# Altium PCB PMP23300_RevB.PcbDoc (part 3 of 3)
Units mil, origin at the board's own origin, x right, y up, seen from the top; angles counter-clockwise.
Board outline 3834 x 2383 mil, 4 copper layers (Top Layer 1, Signal Layer 2, Signal Layer 3, Bottom Layer 1), stack 70.112 mil thick; 203 components, 126 nets, 635 pads, 226 vias.
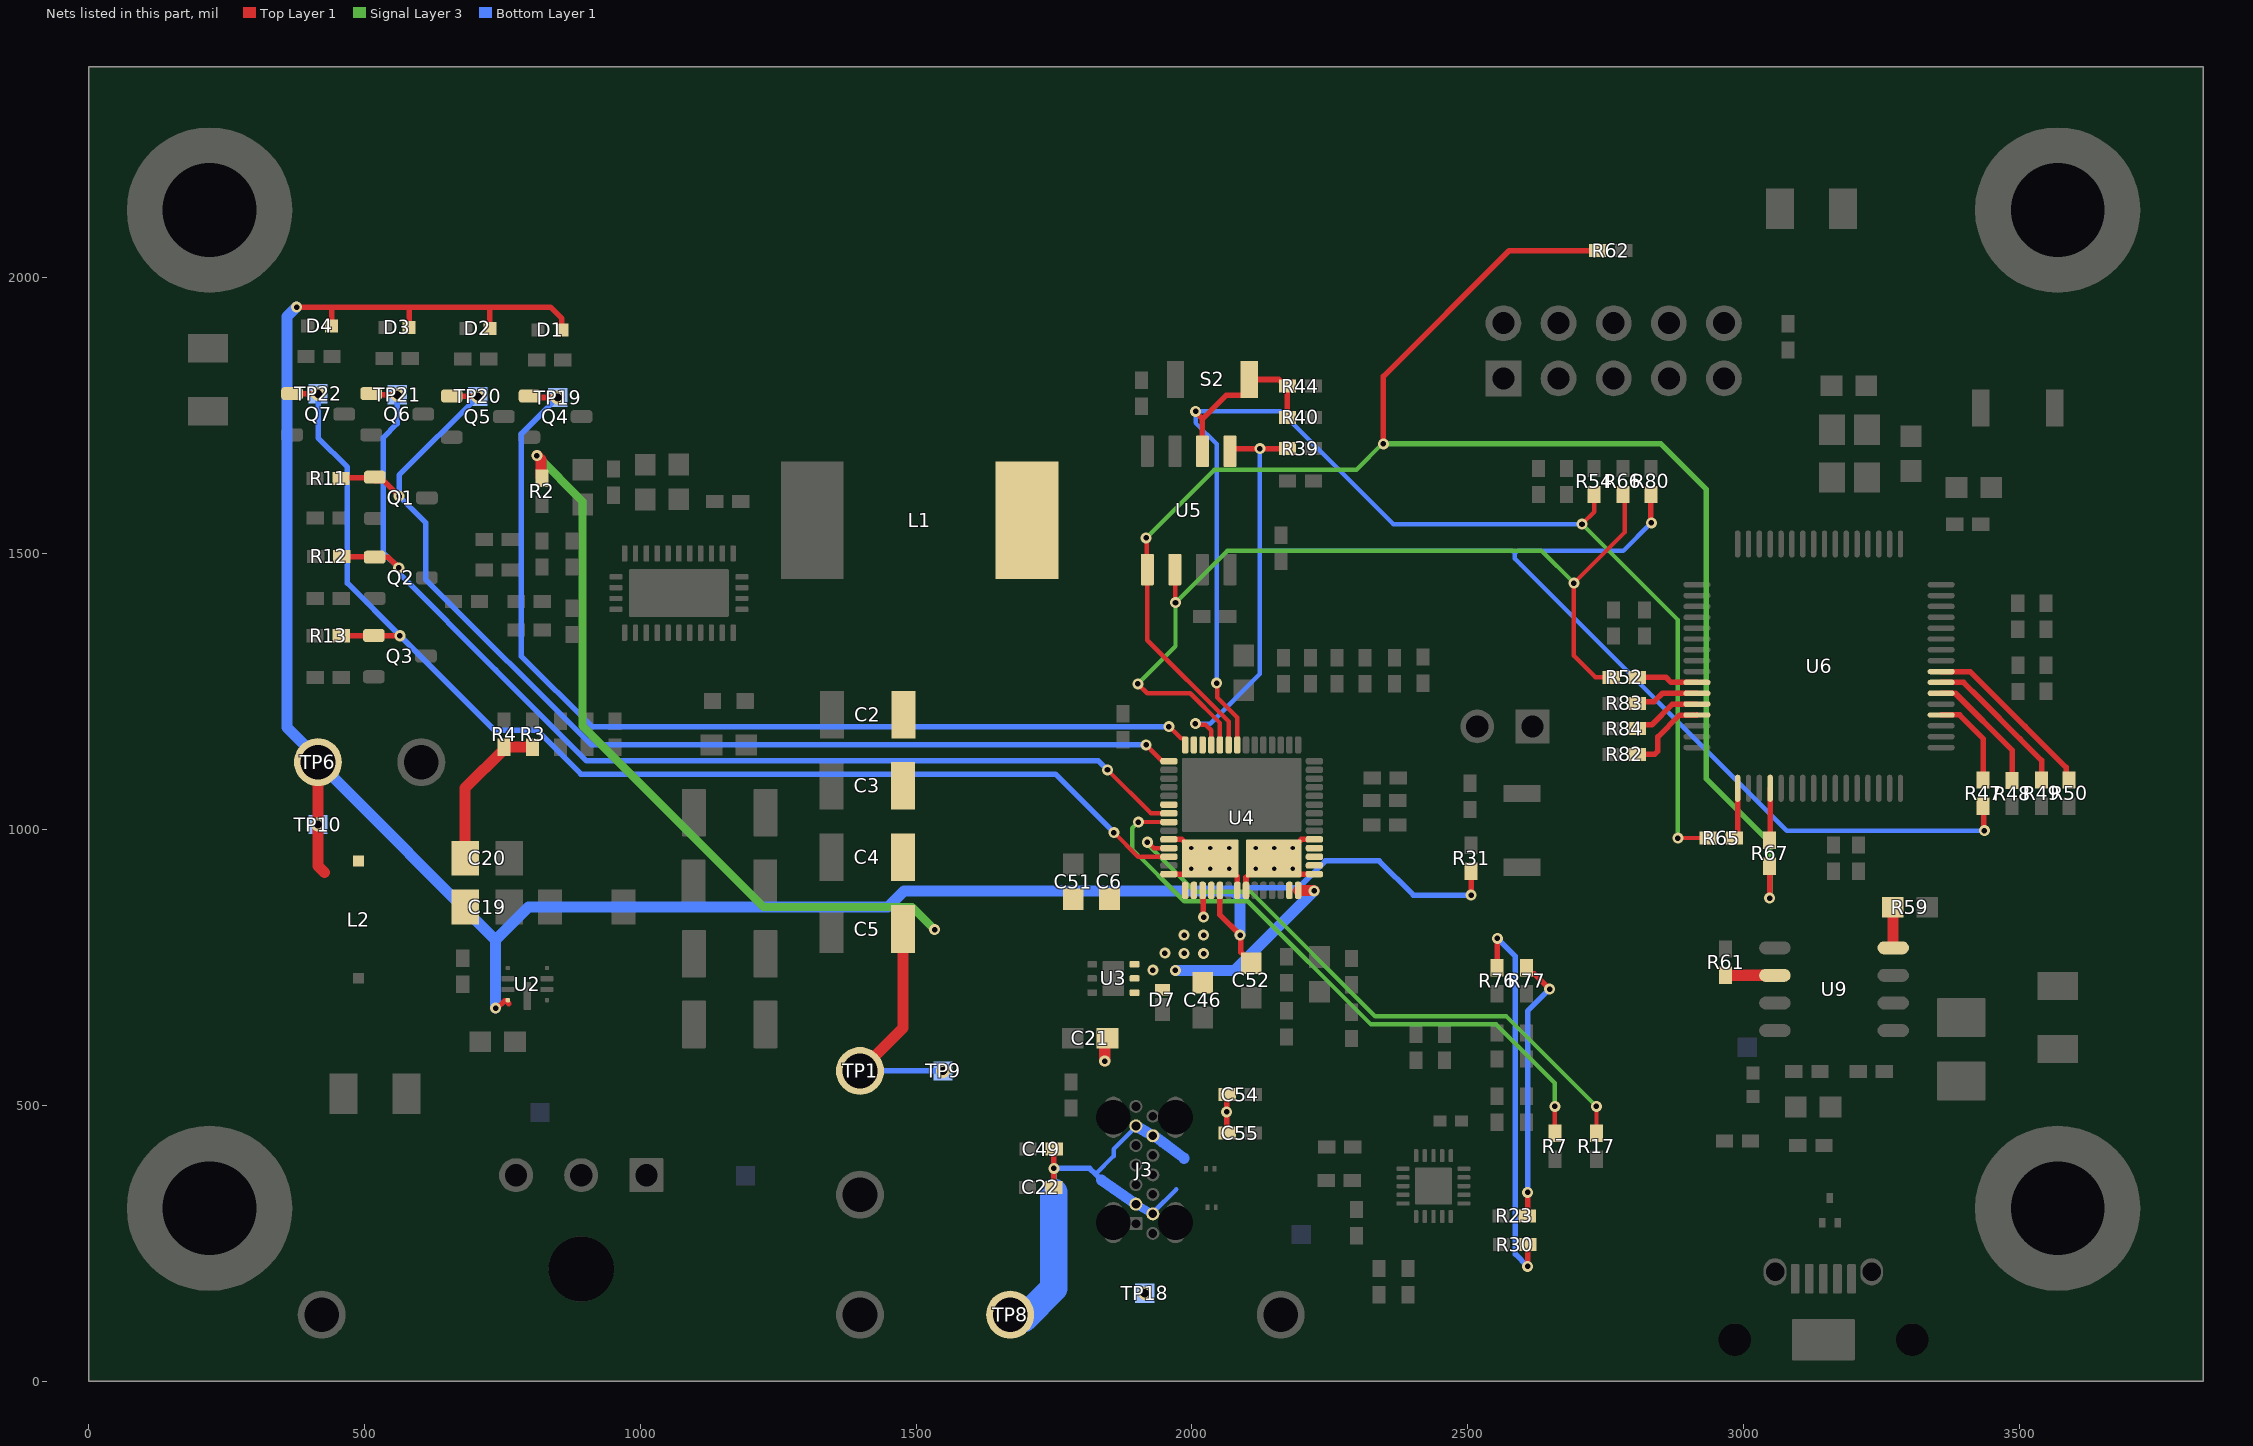
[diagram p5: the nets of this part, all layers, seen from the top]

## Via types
v1: diameter 20, hole 10, Top Layer 1 to Bottom Layer 1, tented top, 93 vias
v2: diameter 20, hole 10, Top Layer 1 to Bottom Layer 1, 67 vias
v3: diameter 19.68, hole 7.87, Top Layer 1 to Bottom Layer 1, 29 vias
v4: diameter 20, hole 10, Top Layer 1 to Bottom Layer 1, tented both sides, 20 vias
v5: diameter 25, hole 15, Top Layer 1 to Bottom Layer 1, 8 vias
v6: diameter 19.68, hole 7.87, Top Layer 1 to Bottom Layer 1, tented both sides, 6 vias
v7: diameter 25, hole 15, Top Layer 1 to Bottom Layer 1, tented top, 3 vias

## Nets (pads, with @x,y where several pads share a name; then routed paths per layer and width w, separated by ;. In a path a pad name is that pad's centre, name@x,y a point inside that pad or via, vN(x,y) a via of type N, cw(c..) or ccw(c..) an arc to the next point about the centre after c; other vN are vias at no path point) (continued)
NetR47_1: R47.1 U6.20 | length 169
  Top Layer 1 w10: U6.20@3358.82,1207.62 3392.25,1207.62 3434.95,1164.92 R47.1@3434.95,1089.71
NetR48_1: R48.1 U6.22 | length 226.3
  Top Layer 1 w10: U6.22@3358.82,1246.99 3384.29,1246.99 3487.28,1144.01 R48.1@3487.28,1088.86
NetR49_1: R49.1 U6.23 | length 276.2
  Top Layer 1 w10: U6.23@3358.82,1266.68 3358.9,1266.6 3399.66,1266.6 3429.65,1236.6 3502.01,1164.25 3540.79,1125.47 R49.1@3540.79,1089.71
NetR50_1: R50.1 U6.24 | length 323.7
  Top Layer 1 w10: U6.24@3358.82,1286.36 3411.44,1286.36 3453.11,1244.7 3510.92,1186.88 3585.16,1112.64 3585.16,1095.54 R50.1@3591,1089.71
NetR52_1: R52.1 U6.58 | length 119.4
  Top Layer 1 w10: R52.1@2812.53,1281.03 R52.1@2807.5,1276 2859.53,1276 2868.94,1266.6 2915.83,1266.6 U6.58@2915.91,1266.68
NetR59_1: R59.1 U9.8 | length 85.2
  Top Layer 1 w20: R59.1@3270.77,858.79 3271.36,858.2 3271.36,786 U9.8@3271.95,785.41 3272.64,786.1 U9.8@3283.04,786.1
NetR61_1: R61.1 U9.2 | length 89.8
  Top Layer 1 w20: R61.1@2967.81,736 2968.11,735.7 3057.09,735.7 U9.2@3057.38,735.41
NetR65_1: R65.1 U6.1 | length 99.2
  Top Layer 1 w10: R65.1@2982.15,993.3 R65.1@2990.93,984.53 ; R65.1@2989.73,987.99 U6.1@2989.73,1074.75
NetR67_1: R67.1 U6.4 | length 98.7
  Top Layer 1 w10: U6.4@3048.78,1074.75 3048.86,1074.67 3048.86,983.14 R67.1@3053.82,978.18
NetR82_1: R82.1 U6.61 | length 153.1
  Top Layer 1 w10: R82.1@2807.5,1136.27 2839.26,1136.27 2845.11,1142.13 2845.11,1167.96 2884.7,1207.54 2915.83,1207.54 U6.61@2915.91,1207.62
NetR83_1: R83.1 U6.59 | length 115.9
  Top Layer 1 w10: R83.1@2807.5,1228.82 2810.37,1231.68 2838.25,1231.68 2853.56,1246.99 U6.59@2915.91,1246.99
NetR84_1: R84.1 U6.60 | length 126.8
  Top Layer 1 w10: R84.1@2807.5,1183.01 2814.31,1189.82 2833.99,1189.82 2871.4,1227.23 2915.83,1227.23 U6.60@2915.91,1227.31
NetU4_7: U4.7 U4.52 U4.56 U4.57@2033.37,947.61 | length 137.4
  Top Layer 1 w10: U4.56@1958.56,919.06 1989.07,919.06 v3(1998.92,928.91) ; U4.52@1958.56,982.05 1982.18,982.05 1997.93,966.31 v3(1998.92,966.31) ; v3(2067.81,928.91) 2068.8,928.91 2082.58,915.13 U4.7@2082.58,889.53
  other v3: 2033.37,928.91 2033.37,966.31 2067.81,966.31
NetU4_8: U4.8 U4.15 U4.19 U4.58@2148.52,947.61 | length 135.2
  Top Layer 1 w10: U4.8@2098.33,889.53 2098.33,913.16 U4.58@2114.07,928.91 ; v6(2182.97,928.91) 2192.81,919.06 U4.15@2222.34,919.06 ; v6(2182.97,966.31) 2198.72,982.05 U4.19@2222.34,982.05
  other v6: 2116.02,928.91 2149.5,928.91 2116.02,966.31 2149.5,966.31
P3V3: C19.1 C20.1 C52.1 D1.1 D2.1 D3.1 D4.1 L2.2 R3.1 R4.1 R31.2 TP6.1 TP10.1 U2.8 U4.5 | length 4802.8
  Top Layer 1 w10: v2(376.92,1947.34) 836.85,1947.34 857.89,1926.3 857.89,1905.93 D1.1@858.04,1905.78 ; D4.1@440.41,1912.96 440.41,1945.48 ; D3.1@580.94,1910.52 580.94,1946.75 ; D2.1@727.38,1908.57 727.38,1946.94 ; v2(737.91,676.08) 740.61,676.08 753.91,689.39 756.71,689.39 761.86,684.23 ; U4.5@2051.08,889.53 2051.08,845.23 2088.98,807.34 2088.98,777.61 2094.61,771.97 C52.1@2104.57,771.97 ; v1(2506.48,881) R31.2@2506.48,924.16
  Top Layer 1 w20: TP6.1@415.57,1122.14 415.57,933.65 427.31,921.91 ; C20.1@682.61,947.94 682.61,1074.95 753.06,1145.4 R4.1@753.06,1149.34 R3.1@804.71,1149.34
  Bottom Layer 1 w10: v7(415.57,1008.91) TP6.1@415.57,1114.11 ; 2087.75,874.54 2107.82,894.61 2193.94,894.61 2242.37,943.03 2339.73,943.03 2401.76,881 v1(2506.48,881)
  Bottom Layer 1 w20: v2(376.92,1947.34) 359.61,1930.03 359.61,1184.67 415.57,1128.71 TP6.1@415.57,1122.14 423.6,1122.14 423.6,1114.11 737.91,799.81 ; v2(737.91,676.08) 737.91,799.81 ; v1(2087.75,808.56) 2087.75,876.98 2076.04,888.69 1478.4,888.69 1449.07,859.36 797.46,859.36 737.91,799.81
PD_USB_N: R17.1 U4.53 | length 1106.7
  Top Layer 1 w8: v2(1919.63,976.88) 1920.24,976.88 1930.81,966.31 U4.53@1958.56,966.31 ; R17.1@2733.79,449.17 v2(2733.79,497.86)
  Signal Layer 3 w8: v2(1919.63,976.88) 1919.63,973.63 1925.37,967.89 1925.37,967.51 2005.41,887.47 2106.29,887.47 2332.68,661.08 2570.57,661.08 v2(2733.79,497.86)
PD_USB_P: R7.1 U4.50 | length 1142.2
  Top Layer 1 w8: v2(1903.07,1013.52) U4.50@1958.55,1013.54 ; R7.1@2658.25,449.27 v1(2658.25,497.86)
  Signal Layer 3 w8: v2(1903.07,1013.52) 1891.79,1002.24 1891.79,964.79 1986.48,870.1 2101.43,870.1 2324.95,646.59 2552,646.59 2658.25,540.33 v1(2658.25,497.86)
PDO_0: Q4.1 TP19.1 U4.42 | length 1813.2
  Top Layer 1 w8: v2(1958.56,1186.41) 1959.73,1186.41 1981.08,1165.06 1986.18,1165.06 1988.09,1163.16 U4.42@1988.09,1153.31
  Top Layer 1 w10: Q4.1@809.29,1783.27 v5(850.16,1783.27)
  Bottom Layer 1 w10: v5(850.16,1783.27) 784.48,1717.59 784.48,1314.07 912.14,1186.41 v2(1958.56,1186.41)
PDO_1: Q1.1 Q5.1 R11.2 TP20.1 U4.43 | length 2055.2
  Top Layer 1 w8: R11.2@457.47,1636.55 R11.2@458.6,1637.68 ; Q1.1@517,1637.68 Q1.1@518.14,1636.55 ; Q1.1@518.7,1632.91 518.7,1637.12 Q1.1@518.7,1638.82 ; v2(1917.26,1153.31) 1933.03,1137.54 1944.88,1125.69 1956.66,1125.69 U4.43@1958.56,1123.79
  Top Layer 1 w10: R11.2@458.6,1637.68 Q1.1@517,1637.68 ; Q1.1@518.14,1636.55 Q1.1@518.7,1637.12 ; Q1.1@518.7,1632.91 519.05,1632.56 534.8,1632.56 v2(562.77,1604.59) ; Q5.1@669.39,1785.53 669.58,1785.34 705.26,1785.34 v5(705.45,1785.15)
  Bottom Layer 1 w10: v5(705.45,1785.15) 562.77,1642.47 v2(562.77,1604.59) 611,1556.36 611,1453.56 910.8,1153.76 1916.81,1153.76 v2(1917.26,1153.31)
PDO_2: Q2.1 Q6.1 R12.2 TP21.1 U4.49 | length 2072.1
  Top Layer 1 w8: R12.2@458.96,1495.1 R12.2@459.65,1494.41 ; Q2.1@517.76,1494.41 Q2.1@518.45,1493.72 ; v2(1847.2,1108.04) 1925.94,1029.3 U4.49@1958.56,1029.3
  Top Layer 1 w10: R12.2@459.65,1494.41 Q2.1@517.76,1494.41 ; Q2.1@518.45,1493.72 532.22,1493.24 543.19,1493.24 557.17,1479.26 v2(562.11,1474.32) ; Q6.1@520.88,1788 v5(559.29,1788)
  Bottom Layer 1 w10: v5(559.29,1788) 559.29,1735.73 533.79,1710.23 533.79,1502.64 564.02,1472.41 564.02,1463.27 737.91,1289.39 902.73,1124.57 1830.67,1124.57 v2(1847.2,1108.04)
PDO_3: Q3.1 Q7.1 R13.2 TP22.1 U4.54 | length 2198.9
  Top Layer 1 w8: v2(1858.81,994.39) 1902.63,950.56 U4.54@1958.56,950.56
  Top Layer 1 w10: Q7.1@380.39,1789.9 v7@415.82,1789.9 ; R13.2@461.19,1351.29 v2(564.21,1351.29)
  Bottom Layer 1 w10: v7(415.85,1789.86) 415.85,1710.12 468.92,1657.05 468.92,1446.58 v2(564.21,1351.29) 735.24,1180.27 812.47,1180.27 892.27,1100.47 1752.72,1100.47 v2(1858.81,994.39)
PP_EXT2_EN: U4.48
SBU_N: R30.1 R76.2 | length 711.6
  Top Layer 1 w10: R76.2@2553.51,747.97 2553.78,748.24 2553.78,802.42 v1(2554.05,802.69) ; v1(2608.88,207.99) R30.1@2608.88,247.25
  Bottom Layer 1 w10: v1(2554.05,802.69) 2586.68,770.06 2586.68,230.19 v1(2608.88,207.99)
SBU_P: R23.1 R77.2 | length 488.3
  Top Layer 1 w10: R77.2@2607.18,749.14 2607.18,745.2 2613.99,738.39 2621.33,738.39 v1(2648.99,710.72) ; R23.1@2608.03,299.41 2608.88,300.26 v1(2608.88,341.98)
  Bottom Layer 1 w10: v1(2608.88,341.98) 2608.88,670.61 v1(2648.99,710.72)
SPI_CLK: R52.2 R66.2 U4.38 U5.6 | length 1653.9
  Top Layer 1 w8: v2(1902.26,1263.86) 1919.05,1247.06 1997.18,1247.06 2051.08,1193.16 U4.38@2051.08,1153.31 ; U5.6@1969.33,1470.32 1969.91,1469.74 1969.91,1411.89 v1(1970.48,1411.32) ; R52.2@2760.26,1276 2731.93,1276 2692.86,1315.07 v2(2692.86,1446.77) 2784.81,1538.71 2784.81,1604.2 R66.2@2781.61,1607.41
  Signal Layer 3 w8: v2(1902.26,1263.86) 1970.48,1332.09 v1(1970.48,1411.32) 2064.27,1505.1 2634.53,1505.1 v2(2692.86,1446.77)
SPI_CSZ: R39.2 R47.2 R80.2 U4.39 U5.1 | length 2621
  Top Layer 1 w8: v2(2006.61,1191.95) 2008.9,1189.66 2025.45,1189.66 2035.33,1179.77 U4.39@2035.33,1153.31
  Top Layer 1 w10: U5.1@2073.27,1690.79 v2(2123.37,1690.79) R39.2@2173.47,1690.79 ; R80.2@2832.61,1607.41 2832.61,1556.83 v4@2833.99,1555.45 ; R47.2@3434.95,1042.46 3435.99,1041.42 3435.99,998.95 v4(3437.03,997.91)
  Bottom Layer 1 w8: v2(2006.61,1191.95) 2033.34,1191.95 2123.37,1281.98 2123.37,1505.1 ; v2(2123.37,1690.79) 2123.37,1505.1 ; v4(2833.3,1556.14) 2782.26,1505.1 2590.61,1505.1 2585.92,1500.41 ; v4(3437.03,997.91) 3078.89,997.91 2597.39,1479.41 2585.92,1490.88 2585.92,1500.41 ; 2123.37,1505.1 2581.24,1505.1 2585.92,1500.41
SPI_MISO: R40.2 R44.2 R54.2 R65.2 S2.1 U4.36 U5.2 | length 2492.3
  Top Layer 1 w8: v1(2045.09,1265.32) 2046.3,1264.11 2046.3,1239.32 2082.58,1203.05 U4.36@2082.58,1153.31 ; v4(2707.56,1553.79) 2729.61,1575.84 R54.2@2729.61,1607.41 ; v4(2881.42,984.53) R65.2@2936.48,984.53
  Top Layer 1 w10: v1@2006.91,1756.32 2019.33,1743.9 ; U5.2@2019.33,1686.85 2019.33,1743.9 ; S2.1@2093.59,1787.46 2062.9,1787.46 2019.33,1743.9 ; S2.1@2104.34,1815.93 2157.72,1815.93 2169.53,1804.12 R44.2@2173.47,1804.12 ; R40.2@2173.47,1747.03 R44.2@2173.47,1804.12 ; R44.2@2184.22,1810.93 2177.41,1804.12 R44.2@2173.47,1804.12
  Signal Layer 3 w8: v4(2707.56,1553.79) 2881.42,1379.93 v4(2881.42,984.53)
  Bottom Layer 1 w8: v1(2045.09,1265.32) 2045.09,1699 2006.91,1737.18 v1(2006.91,1758.25) 2160.67,1758.25 2365.13,1553.79 v4(2707.56,1553.79)
SPI_MOSI: R62.1 R67.2 U4.37 U5.5 | length 3009.5
  Top Layer 1 w8: v2(1917.26,1528.69) 1918.29,1527.65 1918.29,1471.35 1919.33,1470.32 1919.33,1343.29 2066.83,1195.8 U4.37@2066.83,1153.31
  Top Layer 1 w10: v1(2347.48,1699.04) 2347.48,1821.62 2575.61,2049.76 R62.1@2736.05,2049.76 ; v4(3047.75,875.75) R67.2@3047.75,933.42
  Signal Layer 3 w8: v2(1917.26,1528.69) 2041.06,1652.49 2298.62,1652.49 v1@2346.79,1700.66
  Signal Layer 3 w10: v1(2347.48,1699.04) 2850.57,1699.04 2933,1616.6 2933,1091.73 3047.75,976.98 v4(3047.75,875.75)
SSMX_DP: U4.16
SSMX_FLIP: U4.17
SSMX_USB3: U4.18
SWD_CLK: U4.40
SWD_DATA: U4.41
VBUS: C21.2 C22.1 C46.1 C49.1 C54.1 C55.1 D7.1 J3.A4 J3.A9 J3.B4 J3.B9 TP8.1 TP18.1 U3.4 U3.5 U3.6 U4.3 U4.4 U4.13 U4.14 | length 1341.2
  Top Layer 1 w10: C22.1@1749.79,359.08 v1(1749.79,385.71) C49.1@1749.79,412.33 ; J3.A4@1898.73,320.7 J3.A4@1898.73,322.82 ; U4.3@2019.59,889.53 2020.46,888.67 2020.46,842.14 v1(2021.33,841.27) ; C55.1@2063.09,457.77 2063.09,518.3 C54.1@2064.13,519.34 ; U4.14@2192.81,889.53 U4.14@2193.24,889.11 ; v1@2221.55,889.11 v1(2221.98,888.68)
  Top Layer 1 w20: v1(1842.21,579.95) 1842.21,616.56 C21.2@1847.2,621.55 ; U4.14@2193.24,889.11 v1@2221.55,889.11
  Bottom Layer 1 w8: 1825.48,375.05 1858.21,407.78 1858.21,420.4 1898.73,460.92 J3.A9@1898.73,462.43 ; J3.B9@1929.44,305.17 1972.16,347.89
  Bottom Layer 1 w10: 1749.79,342.03 v1(1749.79,385.71) 1814.82,385.71 1825.48,375.05 1836.13,364.4 ; J3.B9@1926.83,305.59 J3.B9@1929.44,302.98 J3.B9@1929.44,305.17
  Bottom Layer 1 w15: J3.A4@1898.73,320.7 J3.B9@1929.44,302.98
  Bottom Layer 1 w20: 1836.13,364.4 J3.A4@1898.73,320.7 ; J3.A9@1898.73,462.43 1919.37,450.52 J3.B4@1929.44,444.71 ; J3.B4@1931.28,444.71 1948.12,432.2 1986.18,403.92 ; v1(1970.35,744.36) 2077.66,744.36 v1(2221.98,888.68)
  Bottom Layer 1 w50: TP8.1@1694.79,113.08 1749.79,168.08 1749.79,342.03
  other v1: 2063.09,488.04 1929.32,745.2 1986.18,775.27 2021.33,774.93 1951.29,775.79 1986.18,808.56 2021.33,808.56
  other v5: 1914.71,159.21
VSYS: C2.1 C3.1 C4.1 C5.1 C6.1 C51.1 L1.2 R2.1 TP1.1 TP9.1 U4.1 U4.2 | length 1817.6
  Top Layer 1 w20: v1(812.47,1677.96) 819.99,1670.44 819.99,1638.64 R2.1@821.8,1636.83 ; TP1.1@1398.47,562.18 1476.33,640.04 C5.1@1476.33,819.51
  Signal Layer 3 w15: v1(812.47,1677.96) 895.41,1595.02 895.41,1187.51 1223.56,859.36 1492.73,859.36 v1(1533.79,818.3)
  Signal Layer 3 w20: TP1.1@1382.15,562.18 TP1.1@1398.47,562.18
  Bottom Layer 1 w10: TP1.1@1398.47,562.18 v5(1549.05,562.18)
pads on no net: J1. J2.4 J5.4 J5.6 LBL1.0 U1.7 U1.23 U1.31A U2.2 U3.7@1857.8,712.14 U3.7@1857.8,747.58 U4.57@2006.79,947.61 U4.57@2059.94,947.61 U4.58@2121.95,947.61 U4.58@2175.1,947.61 U4.59@2012.5,1029.89 U4.59@2012.5,1095.64 U4.59@2064.47,1029.89 U4.59@2064.47,1095.64 U4.59@2116.44,1029.89 U4.59@2116.44,1095.64 U4.59@2168.41,1029.89 U4.59@2168.41,1095.64 U6.5 U6.6 U6.7 U6.8 U6.9 U6.10 U6.13 U6.14 U6.15 U6.16 U6.17 U6.18 U6.19 U6.21 U6.28 U6.29 U6.30 U6.31 U6.33 U6.36 U6.45 U6.46 U6.47 U6.48 U6.49 U6.50 U6.51 U6.52 U6.53 U6.57 U6.62 U6.63 U6.64 U9.7 U10.21@2419.52,334.7 U10.21@2419.52,372.11 U10.21@2456.92,334.7 U10.21@2456.92,372.11

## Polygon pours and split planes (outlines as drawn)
GND on Top Layer 1 "TOP_LAYER_1_GND_P015" (solid, remove dead copper, pour order 15): 315.79,636.09 397.22,717.52 397.22,1177.78 168.45,1406.55 168.45,2170.74 3615.59,2170.74 3615.59,-3.92 315.79,-3.92
F_VBUS on Top Layer 1 "TOP_LAYER_1_F_VBUS_P010" (solid, remove dead copper, pour order 10): 3115.45,478.16 3065.58,478.16 3065.58,506.06 3039.02,532.62 2955.8,532.62 2955.8,634.34 3026.52,705.06 3084.67,705.06 3115.45,674.28 3115.45,535.61
F_SYS_3V3 on Top Layer 1 "f_sys" (solid, remove dead copper, pour order 0): 3453.66,923.3 3394.26,982.71 3304.2,982.71 3304.2,974.74 3325.87,953.06 3325.87,923.3 3325.87,707.83 3323.1,705.06 3232,705.06 3232,548.48 3239.78,540.7 3281.01,540.7 3300.36,560.05 3353.64,613.33 3446.83,613.33 3454.47,620.96 3454.47,923.3
VBUS on Top Layer 1 "TOP_LAYER_1_VBUS_P009" (solid, remove dead copper, pour order 9): 1886.38,761.81 1891.5,766.93 1906.5,766.93 2003.84,864.27 2003.84,905.29 2040.99,905.29 2040.99,701.58 2037.33,697.91 1886.38,697.91
VSYS on Top Layer 1 "TOP_LAYER_1_VSYS_P006" (solid, remove dead copper, pour order 6): 1784.93,1038.43 1749.41,1002.92 1749.41,917.55 1761.68,905.29 1860.21,905.28 2019.59,905.28 2019.59,880.53 1913.78,775.08 1453.79,775.08 1444.26,784.62 1444.26,1265.45 1444.26,1359.94 1542.49,1458.18 1542.49,1694.88 1554.2,1706.44 1772.43,1706.44 1784.93,1693.94
NetC13_1 on Top Layer 1 "TOP_LAYER_1_NETC13_1_P004" (solid, remove dead copper, pour order 4): 1131.7,1560.51 1154.04,1560.51 1164.1,1570.58 1164.1,1614.81 1185.99,1614.81 1261.13,1689.94 1385.43,1689.94 1398.47,1676.91 1398.47,1454.86 1389.81,1446.2 1246.01,1446.2 1212.38,1479.83 1089.74,1479.83 1084.7,1484.87 1084.7,1513.52
P3V3 on Top Layer 1 "TOP_LAYER_1_P3V3_P003" (solid, remove dead copper, pour order 3): 355.44,859.36 600.35,859.36 640.35,819.36 711.15,819.36 722.61,830.82 720.95,832.48 720.95,999.51 711.55,1008.91 373.56,1008.91 357.86,993.2
NetC16_1 on Top Layer 1 "TOP_LAYER_1_NETC16_1_P002" (solid, remove dead copper, pour order 2): 777.61,743.15 777.61,767.14 752.38,792.37 745.6,799.15 355.44,799.15 355.44,702.69 364.19,693.94 620.1,693.94 638.95,712.79 638.95,733.21 648.89,743.15
NetC8_2 on Top Layer 1 "TOP_LAYER_1_NETC8_2_P001" (solid, remove dead copper, pour order 1): 955.88,671.66 955.88,302.08 1154.74,302.08 1154.74,1275.88 1099.09,1331.54 1099.09,1374.79 1096.26,1377.62 1077.56,1377.62 1047,1377.62 1042.27,1372.9 1042.27,1329.51 989.35,1276.59 989.35,1192.11 970.2,1172.96 932.55,1172.96 915.32,1155.74 915.32,818.3 857.98,818.3 813.04,773.36 813.04,738.51 829.91,721.65 905.89,721.65
NetU4_8 on Bottom Layer 1 "BOTTOM_LAYER_1_NETU4_8_P008" (solid, remove dead copper, pour order 8): 2101.16,911.94 2101.16,984.53 2198.1,984.52 2198.1,918.8 2191.24,911.94
NetU4_7 on Bottom Layer 1 "BOTTOM_LAYER_1_NETU4_7_P018" (solid, remove dead copper, pour order 18): 1978.78,984.15 1978.78,911.55 2093,911.55 2093,984.15
GND on Bottom Layer 1 "BOTTOM_LAYER_1_GND_P020" (solid, remove dead copper, pour order 20): 315.79,-3.92 3540.79,-3.92 3540.79,2136.08 315.79,2136.08
VBUS on Bottom Layer 1 "BOTTOM_LAYER_1_VBUS_P019" (solid, remove dead copper, pour order 19): 2090.45,164.29 2090.45,763.44 2063.09,790.8 2063.09,866.49 1978.78,866.22 1726.76,614.19 1726.76,164.29
GND on Signal Layer 2 "SIGNAL_LAYER_2_GND_P013" (solid, remove dead copper, pour order 13): 168.45,-3.92 3540.79,-3.92 3540.79,2173.33 168.45,2173.33
GND on Signal Layer 3 "SIGNAL_LAYER_3_GND_P016" (solid, remove dead copper, pour order 16): 168.45,-3.92 3607.08,-3.92 3607.08,2173.33 168.45,2173.33

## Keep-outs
Keep-Out Layer:
  text ".Layer_Name" at 577,-858.49 h60

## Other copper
Top Layer 1:
  text ".Layer_Name" at 577,-858.49 h60
Bottom Layer 1:
  text ".Layer_Name" at 577,-858.49 h60

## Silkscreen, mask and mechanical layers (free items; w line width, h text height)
Top Overlay:
  lines w5: 910.01,1458.18 910.01,1539.94 ; 1589.49,1822.6 1589.49,1904.36
  text "20V" at 375.5,1976.57 h35
  text "15V" at 517.29,1976.57 h35
  text "9V" at 668.43,1976.57 h35
  text "5V" at 802.61,1976.57 h35
  text "'.PRJ_Number'.PCB_Rev" at 208,670 h108.27 r90
  text "Max output:" at 2439.5,96.7 h35
  text "30-60 VDC" at 599.64,58.1 h35 r90
  text "20V/3A" at 2456.41,40.85 h35
  text ".Layer_Name" at 577,-858.49 h35
Bottom Overlay:
  text ".Layer_Name" at 577,-858.49 h60
Top Paste:
  text ".Layer_Name" at 577,-858.49 h60
Bottom Paste:
  text ".Layer_Name" at 577,-858.49 h60
Top Solder:
  text ".Layer_Name" at 577,-858.49 h60
  text ".Layer_Name" at 577,-858.49 h60
Bottom Solder:
  text ".Layer_Name" at 577,-858.49 h60
Drill Guide:
  text ".Layer_Name" at 577,-858.49 h60
M1 Board Outline:
  the board outline again, w10
  text ".Layer_Name" at 577,-858.49 h60
M2 Board Dimensions:
  rectangle: 0,-275 125,-150
  rectangle: 125,-400 500,-275
  lines w7: 0,-275 1000,-275 ; 125,-400 125,-150 ; 250,-400 250,-150 ; 500,-400 500,-150 ; 750,-400 750,-150 ; 0,-400 1000,-400 1000,-150 0,-150 0,-400
  text ".Layer_Name" at 577,-858.49 h60
M3 3D STEP Top:
  text ".Layer_Name" at 577,-858.49 h60
M4 3D STEP Bottom:
  text ".Layer_Name" at 577,-858.49 h60
M5 Assembly Top:
  lines w10: -292,-930.17 6308,-930.17 ; -292,-726.83 6310,-726.83 ; -292,-523.5 -292,-1133.5 3713,-1133.5 6310,-1133.5 6310,-523.5 -291.5,-523.5 -291.5,-1133.5 1284,-1133.5 ; 2173,-1133.5 2173,-523.5 ; 3440,-726.83 3440,-523.5 ; 4280,-726.83 4280,-523.5 ; 4902,-1140 4902,-937.17
  text "COMPONENTS MARKED 'DNP' SHOULD NOT BE POPULATED." at 1153.5,-318.5 h60
  text "ASSEMBLY VARIANT:" at 1153,-434 h60
  text ".VariantName" at 2189,-434 h60
  text "PCB VIEWED FROM TOP SIDE" at -228.5,-655.67 h60
  text "BOARD #:" at 2248,-655.67 h60
  text ".PRJ_Number" at 2793.5,-655.67 h60
  text "REV:" at 3638,-655.67 h60
  text ".PCB_Rev" at 3929.5,-655.67 h60
  text "SVN REV:" at 4476,-655.67 h60
  text ".VersionControl_RevNumber" at 4982,-655.67 h60
  text "TID #:" at 2248,-859 h60
  text ".TID" at 2793.5,-859 h60
  text "PLOT NAME =" at -228.5,-1064.34 h60
  text ".plot_File_Name" at 577,-1064.34 h60
  text "GENERATED    :" at 2250,-1064.34 h60
  text ".Print_Date" at 3119.5,-1064.34 h60
  text ".Print_Time" at 3848.5,-1064.34 h60
  text "TEXAS INSTRUMENTS" at 5113,-1064.34 h60
M6 Assembly Bottom:
  lines w10: -292.5,-727.33 6309.5,-727.33 ; -290.5,-930.67 6309.5,-930.67 ; 1115.5,-1140.5 1115.5,-937.67 ; 1737.5,-727.33 1737.5,-524 ; 2577.5,-727.33 2577.5,-524 ; 3844.5,-1134 3844.5,-524 ; 4733.5,-1134 6309,-1134 6309,-524 -292.5,-524 -292.5,-1134 2304.5,-1134 6309.5,-1134 6309.5,-524
  text "COMPONENTS MARKED 'DNP' SHOULD NOT BE POPULATED." at 6102,-318 h60
  text ".VariantName" at 5058,-434 h60
  text "ASSEMBLY VARIANT:" at 6097,-434 h60
  text ".VersionControl_RevNumber" at 1035.5,-656.17 h60
  text "SVN REV:" at 1541.5,-656.17 h60
  text ".PCB_Rev" at 2088,-656.17 h60
  text "REV:" at 2379.5,-656.17 h60
  text ".PRJ_Number" at 3224,-656.17 h60
  text "BOARD #:" at 3769.5,-656.17 h60
  text "PCB VIEWED FROM BOTTOM SIDE" at 6246,-656.17 h60
  text ".TID" at 3224,-859.5 h60
  text "TID #:" at 3769.5,-859.5 h60
  text "TEXAS INSTRUMENTS" at 904.5,-1064.84 h60
  text ".Print_Time" at 2169,-1064.84 h60
  text ".Print_Date" at 2898,-1064.84 h60
  text "GENERATED    :" at 3767.5,-1064.84 h60
  text ".plot_File_Name" at 5440.5,-1064.84 h60
  text "PLOT NAME =" at 6246,-1064.84 h60
M9 Title Sheet:
  drawing of 57 lines, arcs and shapes, not listed
  text "1" at 739.84,8036.5 h70
  text "2" at 3235.5,8036.5 h70
  text "3" at 5724.84,8036.5 h70
  text "4" at 8231.51,8036.5 h70
  text "5" at 10730.5,8036.5 h70
  text "6" at 13235.5,8036.5 h70
  text "A" at -416.5,6893.5 h70
  text "A" at 14383.5,6893.5 h70
  text "B" at -416.5,4513.5 h70
  text "B" at 14383.5,4513.5 h70
  text "C" at -416.5,2138.5 h70
  text "C" at 14383.5,2138.5 h70
  text "PROJECT TITLE:" at 11343.5,277.5 h45
  text ".PRJ_Title" at 11393.5,144.17 h70
  text "DESIGNED FOR:" at 11343.5,-23.5 h45
  text ".PRJ_Customer" at 11393.5,-163.5 h70
  text "D" at -416.5,-231.5 h70
  text "D" at 14383.5,-231.5 h70
  text "FILE NAME:" at 11343.5,-323.5 h45
  text ".PCB_File_Name_No_Path" at 11393.5,-443.5 h70
  text "Texas Instruments (TI) and/or its licensors do not warrant the accuracy or completeness of this specification" at 6374,-605.34 h45
  text "ENGINEER:" at 11343.5,-613.5 h45
  text "LAYOUT BY:" at 12848.5,-613.5 h45
  text "or any information contained therein. TI and/or its licensors do not warrant that this design will meet" at 6329.01,-718 h45
  text ".PRJ_Engineer" at 11393.5,-768.49 h70
  text ".PCB_Layout" at 12899,-768.49 h70
  text "the specifications, will be suitable for your application or fit for any particular purpose, or will operate in" at 6329.01,-830.67 h45
  text ".Layer_Name" at 577,-858.49 h60
  text "ALTIUM DESIGNER VERSION:" at 12848.5,-923.5 h45
  text "an implementation. TI and/or its licensors do not warrant that the design is production worthy. You should" at 6329.01,-943.33 h45
  text "completely validate and test your design implementation to confirm the system functionality for your application." at 6374,-1056 h45
  text ".print_Scale" at 11393.5,-1056.83 h70
  text ".Application_BuildNumber" at 12899,-1056.83 h70
  text "1" at 739.84,-1263.5 h70
  text "2" at 3235.5,-1263.5 h70
  text "3" at 5724.84,-1263.5 h70
  text "4" at 8231.51,-1263.5 h70
  text "5" at 10730.5,-1263.5 h70
  text "6" at 13235.5,-1263.5 h70
M10 Fab Notes:
  drawing of 189 lines, arcs and shapes, not listed
  text "DESIGN INFORMATION" at 12382.02,6356.17 h60
  text "MIN. TRACK WIDTH:" at 11737.46,6224.05 h60
  text "8" at 12833.7,6224.05 h60
  text "MIL" at 12988.46,6224.05 h60
  text "7.874" at 12667.32,6102.36 h60
  text "MIN. CLEARANCE:" at 11737.46,6099.92 h60
  text "MIL" at 12988.46,6099.92 h60
  text "MIN. VIA PAD SIZE:" at 11737.46,5975.8 h60
  text "24" at 12803.71,5975.8 h60
  text "MIL" at 12988.46,5975.8 h60
  text "0.05mm (2MIL)" at 12432.46,5845.9 h60
  text "MINIMUM ANNULAR RING" at 11408.23,5837.67 h60
  text "EXTERNAL" at 13140.46,5837.67 h60
  text "PER" at 11608.23,5727.55 h60
  text "IPC-D-275 CLASS 2 LEVEL C" at 11828.23,5727.54 h60
  text "MIL, HOLES" at 13316.46,5627.07 h60
  text "+/-" at 12924,5618.48 h60
  text "+/-" at 13778,5618.48 h60
  text "REGISTRATION TOLERANCES:" at 11408.23,5617.42 h60
  text "METAL" at 12608,5617.42 h60
  text "5" at 13184.2,5617.42 h60
  text "3" at 14017.2,5617.42 h60
  text "MIL" at 14133.46,5617.42 h60
  text "HOLE SIZE TOLERANCE (UNLESS OTHERWISE SPECIFIED):" at 11408.23,5519.1 h60
  text "+/-" at 13778,5516.23 h60
  text "3" at 14017.2,5515.17 h60
  text "MIL" at 14133.46,5515.17 h60
  text "MATERIAL:" at 11333.46,5377.52 h60
  text "FR-4 High Tg" at 12319.9,5249 h60
  text "X" at 12175.46,5241.01 h60
  text "FR-408" at 11754.46,5236.49 h60
  text "OTHER" at 13242.46,5236.49 h60
  text "62 MIL (1.6mm) +/-10%" at 12074.56,5093.46 h60
  text "X" at 11954.46,5091.01 h60
  text "THICKNESS:" at 11408.23,5085.24 h60
  text "OTHER" at 13359.46,5085.24 h60
  text "TOLERANCE:" at 11408.23,4946.92 h60
  text "X" at 12256.46,4946.92 h60
  text "ANSI IPC-6012 TYPE 3 CLASS 2" at 12434.48,4946.92 h60
  text "OTHER +/-" at 12434.46,4802.73 h60
  text "BOW & TWIST:" at 11408.23,4657.54 h60
  text "X" at 12256.46,4657.54 h60
  text "ANSI IPC-6012 TYPE 3 CLASS 2" at 12434.48,4657.54 h60
  text "OTHER +/-" at 12434.46,4510.85 h60
  text "DRILLING:" at 11333.46,4380.23 h60
  text "NC_DRILL FILES" at 13094.46,4275.04 h60
  text "REFERENCE:" at 11408.23,4271.1 h60
  text "X" at 12065.46,4271.01 h60
  text "AS SHOWN" at 12243.46,4271.1 h60
  text "X" at 12966.46,4271.1 h60
  text "OTHER" at 13392.46,4128.85 h60
  text "PTH COPPER THICKNESS:" at 11407.91,4125.32 h60
  text "X" at 12547.14,4125.32 h60
  text "20-30 um" at 12675.14,4125.32 h60
  text "BOARD FINISH:" at 11333.46,3977.73 h60
  text "SILKSCREEN:" at 11488.68,3867.6 h60
  text "X" at 12446.46,3867.6 h60
  text "TOP" at 12563.46,3867.6 h60
  text "X" at 12956.46,3867.6 h60
  text "BOTTOM" at 13074.46,3867.6 h60
  text "SILKSCREEN COLOR:" at 11488.68,3712.41 h60
  text "X" at 12445.46,3712.41 h60
  text "WHITE" at 12563.46,3712.41 h60
  text "OTHER" at 13074.46,3712.41 h60
  text "X" at 12576.46,3568.96 h60
  text "GREEN" at 12694.46,3568.96 h60
  text "OTHER" at 13312.46,3568.96 h60
  text "SOLDER RESIST COLOR:" at 11488.68,3562.1 h60
  text "X" at 12576.46,3414.71 h60
  text "MATTE" at 12694.46,3414.71 h60
  text "SEMI-GLOSS" at 13312,3414.07 h60
  text "IMMERSION GOLD (ENIG)" at 12394.46,3241.94 h60
  text "ENEPIG" at 13732,3234.72 h60
  text "SURFACE FINISH:" at 11333.46,3233.72 h60
  text "X" at 12216.46,3233.72 h60
  text "IMM. TIN/SILVER OR EQUIV" at 11663,3096.4 h60
  text "OTHER" at 13094.46,3092.47 h60
  text "ARRAY/PANEL:" at 11333.46,2937.09 h60
  text "CUT AND TRIM PER M1 BOARD OUTLINE" at 12394.46,2928.87 h60
  text "N.C. ROUTE" at 12394.46,2792.9 h60
  text "X" at 13082.46,2792.9 h60
  text "V. SCORE" at 13260.46,2792.9 h60
  text "CERTIFICATION:" at 11333.46,2663.77 h60
  text "MATERIALS AND WORKMANSHIP FOR ALL PCBS" at 12058.46,2663.77 h60
  text "TO MEET OR EXCEED THE REQUIREMENTS OF:" at 12058.46,2569.71 h60
  text "X" at 11695.97,2441.08 h60
  text "ANSI IPC-A-600F CLASS ->" at 11823.96,2441.08 h60
  text "X" at 13471.97,2441.08 h60
  text "2" at 13581.96,2441.08 h60
  text "1" at 13266.96,2439.58 h60
  text "3" at 13935.96,2439.58 h60
  text "X" at 12507.97,2293.39 h60
  text "RoHS" at 12635.96,2293.39 h60
  text "OTHER" at 13280.36,2293.39 h60
  text "PER ORDER" at 13677.42,2293.39 h60
  text "ALL BOARDS MUST MEET OR EXCEED UL94-V0 REQUIREMENTS." at 11361,2139.57 h60
  text "PCB MUST BEAR THE UL94V-0 UL REGISTERED MATERIAL ID NUMBER" at 11361,2023.5 h60
  text "ADDITIONAL REQUIREMENTS:" at 11333.46,1854.08 h60
  text "MICROSECTION:" at 11408.23,1746.95 h60
  text "YES" at 12313.96,1746.95 h60
  text "REQUIRED" at 13175.46,1602.62 h60
  text "BARE BOARD ELEC. TEST:" at 11408.23,1599.76 h60
  text "NONE" at 12713.96,1599.76 h60
  text "X" at 13057.46,1599.76 h60
  text "PER ORDER" at 13767.46,1599.76 h60
  text "XX MIL VIAS REQUIRE NON-CONDUCTIVE FILL AND PLANARIZE" at 11576.38,1394.82 h59
  text "XX MIL VIAS REQUIRE CONDUCTIVE FILL AND PLANARIZE" at 11584.38,1290.84 h60
  text "OUTER XX MIL TRACES REQUIRE 50 OHM SINGLE-ENDED IMPEDANCE" at 11583.39,1127.46 h58
  text "LAYER 2 & 3 (INNER LAYERS) XX MIL WIDE, XX MIL SPACE / TRACES REQUIRE 100 OHM DIFFERENTIAL IMPEDANCE" at 11575.39,891.74 h60
  text ".Layer_Name" at 577,-858.49 h60
M11 Gerber Information:
  lines w10: -292,-930.17 6308,-930.17 ; -292,-726.83 6310,-726.83 ; -292,-523.5 -292,-1133.5 3713,-1133.5 6310,-1133.5 6310,-523.5 -291.5,-523.5 -291.5,-1133.5 1284,-1133.5 ; 2173,-1133.5 2173,-523.5 ; 3440,-726.83 3440,-523.5 ; 4280,-726.83 4280,-523.5 ; 4902,-1140 4902,-937.17
  text "ALL ARTWORK VIEWED FROM TOP SIDE" at -228.5,-655.67 h60
  text "BOARD #:" at 2248,-655.67 h60
  text ".PRJ_Number" at 2793.5,-655.67 h60
  text "REV:" at 3638,-655.67 h60
  text ".PCB_Rev" at 3929.5,-655.67 h60
  text "SVN REV:" at 4476,-655.67 h60
  text ".VersionControl_RevNumber" at 4982,-655.67 h60
  text "LAYER NAME =" at -228.5,-858.49 h60
  text "TID #:" at 2248,-859 h60
  text ".TID" at 2793.5,-859 h60
  text "PLOT NAME =" at -228.5,-1064.34 h60
  text ".plot_File_Name" at 577,-1064.34 h60
  text "GENERATED    :" at 2250,-1064.34 h60
  text ".Print_Date" at 3119.5,-1064.34 h60
  text ".Print_Time" at 3848.5,-1064.34 h60
  text "TEXAS INSTRUMENTS" at 5113,-1064.34 h60
M12 Stackup:
  drawing of 347 lines, arcs and shapes, not listed
  text "Layer" at 9821.59,7874.94 h60
  text "Name" at 10231.51,7874.94 h60
  text "Material" at 11561.12,7874.94 h60
  text "Thickness" at 12160.97,7874.94 h60
  text "Constant" at 12810.81,7874.94 h60
  text "Board Layer Stack" at 13380.67,7874.94 h60
  text "Top Overlay" at 10231.51,7754.94 h60
  text "Top Solder" at 10231.51,7634.94 h60
  text "SM-001" at 11561.12,7634.94 h60
  text "1.00mil" at 12160.97,7634.94 h60
  text "4" at 12810.81,7634.94 h60
  text "Top Surface Finish" at 10231.51,7514.94 h60
  text "PbSn" at 11561.12,7514.94 h60
  text "0.79mil" at 12160.97,7514.94 h60
  text "1" at 9821.59,7394.94 h60
  text "Top Layer 1" at 10231.51,7394.94 h60
  text "CF-004" at 11561.12,7394.94 h60
  text "1.38mil" at 12160.97,7394.94 h60
  text "Dielectric 2" at 10231.51,7274.94 h60
  text "PP-006" at 11561.12,7274.94 h60
  text "2.80mil" at 12160.97,7274.94 h60
  text "4.1" at 12810.81,7274.94 h60
  text "2" at 9821.59,7154.94 h60
  text "Signal Layer 2" at 10231.51,7154.94 h60
  text "CF-004" at 11561.12,7154.94 h60
  text "1.38mil" at 12160.97,7154.94 h60
  text "Dielectric 1" at 10231.51,7034.94 h60
  text "Core-043" at 11561.12,7034.94 h60
  text "59.00mil" at 12160.97,7034.94 h60
  text "4.3" at 12810.81,7034.94 h60
  text "3" at 9821.59,6914.94 h60
  text "Signal Layer 3" at 10231.51,6914.94 h60
  text "CF-004" at 11561.12,6914.94 h60
  text "1.38mil" at 12160.97,6914.94 h60
  text "Dielectric 3" at 10231.51,6794.94 h60
  text "PP-006" at 11561.12,6794.94 h60
  text "2.80mil" at 12160.97,6794.94 h60
  text "4.1" at 12810.81,6794.94 h60
  text "4" at 9821.59,6674.94 h60
  text "Bottom Layer 1" at 10231.51,6674.94 h60
  text "CF-004" at 11561.12,6674.94 h60
  text "1.38mil" at 12160.97,6674.94 h60
  text "Bottom Surface Finish" at 10231.51,6554.94 h60
  text "PbSn" at 11561.12,6554.94 h60
  text "0.79mil" at 12160.97,6554.94 h60
  text "Bottom Solder" at 10231.51,6434.94 h60
  text "SM-001" at 11561.12,6434.94 h60
  text "1.00mil" at 12160.97,6434.94 h60
  text "4" at 12810.81,6434.94 h60
  text "Bottom Overlay" at 10231.51,6314.94 h60
  text ".Layer_Name" at 577,-858.49 h60
M13 Component Bodies Top:
  text ".Layer_Name" at 577,-858.49 h60
M14 Component Bodies Bottom:
  text ".Layer_Name" at 577,-858.49 h60
M15 Courtyards Top:
  text ".Layer_Name" at 577,-858.49 h60
M16 Courtyards Bottom:
  text ".Layer_Name" at 577,-858.49 h60
Drill Drawing:
  circle w10: c6533.31,7401.52 r16.58
  circle w10: c6533.31,7401.52 r27.63
  circle w10: c6533.31,6406.96 r27.63
  lines w10: 6505.68,6517.46 6519.5,6517.46 6533.31,6503.65 6547.12,6517.46 6560.94,6517.46 6547.12,6531.28 6560.94,6545.09 6547.12,6545.09 6533.31,6558.9 6519.5,6545.09 6505.68,6545.09 6519.5,6531.28 6505.68,6517.46 ; 6505.68,6627.97 6533.31,6641.78 6560.94,6627.97 6547.12,6655.6 6560.94,6683.22 6533.31,6669.41 6505.68,6683.22 6519.5,6655.6 6505.68,6627.97 ; 6505.68,6766.1 6519.5,6766.1 6533.31,6752.29 6547.12,6766.1 6560.94,6766.1 6547.12,6779.92 6560.94,6793.73 6547.12,6793.73 6533.31,6807.54 6519.5,6793.73 6505.68,6793.73 6519.5,6779.92 6505.68,6766.1 ; 6505.68,6876.61 6560.94,6876.61 6560.94,6931.86 6505.68,6931.86 6505.68,6876.61 ; 6505.68,7000.93 6505.68,7014.74 6519.5,7028.56 6505.68,7042.37 6505.68,7056.18 6519.5,7056.18 6533.31,7042.37 6547.12,7056.18 6560.94,7056.18 6560.94,7042.37 6547.12,7028.56 6560.94,7014.74 6560.94,7000.93 6547.12,7000.93 6533.31,7014.74 6519.5,7000.93 6505.68,7000.93 ; 6505.68,7180.5 6560.94,7180.5 6533.31,7125.25 6505.68,7180.5 ; 6505.68,7304.82 6560.94,7304.82 6533.31,7249.57 6505.68,7304.82 ; 6505.68,7498.21 6560.94,7498.21 6560.94,7553.46 6505.68,7553.46 6505.68,7498.21 ; 6505.68,7650.16 6533.31,7622.53 6560.94,7650.16 6533.31,7677.78 6505.68,7650.16 ; 6505.68,7760.66 6519.5,7760.66 6519.5,7746.85 6547.12,7746.85 6547.12,7760.66 6560.94,7760.66 6560.94,7788.29 6547.12,7788.29 6547.12,7802.1 6519.5,7802.1 6519.5,7788.29 6505.68,7788.29 6505.68,7760.66 ; 6516.74,6771.63 6525.02,6771.63 6533.31,6763.34 6541.6,6771.63 6549.89,6771.63 6541.6,6779.92 6549.89,6788.2 6541.6,6788.2 6533.31,6796.49 6525.02,6788.2 6516.74,6788.2 6525.02,6779.92 6516.74,6771.63 ; 6516.74,7169.45 6549.89,7169.45 6533.31,7136.3 6516.74,7169.45 ; 6516.74,7509.26 6549.89,7509.26 6549.89,7542.41 6516.74,7542.41 6516.74,7509.26
  lines w12: 6455.59,6342.03 9767.22,6342.03 ; 6455.59,7833.87 9767.22,7833.87 ; 6793.46,6217.71 6793.46,7958.19 ; 7125.46,6217.71 7125.46,7958.19 ; 7762.02,6217.71 7762.02,7958.19 ; 8021.16,6217.71 8021.16,7958.19 ; 8396.32,6217.71 8396.32,7958.19 ; 9200.79,6217.71 9200.79,7958.19 ; 6455.59,6217.71 9767.22,6217.71 9767.22,7958.19 6455.59,7958.19 6455.59,6217.71
  text "Symbol" at 6530.19,7871.17 h72
  text "Quantity" at 6830.75,7871.17 h72
  text "Finished Hole Size" at 7162.75,7871.17 h72
  text "Plated" at 7799.32,7871.17 h72
  text "Hole Type" at 8058.46,7871.17 h72
  text "Drill Layer Pair" at 8433.61,7871.17 h72
  text "Hole Tolerance" at 9238.09,7871.17 h72
  text "1" at 6830.75,7746.85 h60
  text "118.11mil (3.000mm)" at 7162.75,7746.85 h60
  text "NPTH" at 7799.32,7746.85 h60
  text "Round" at 8058.46,7746.85 h60
  text "Top Layer 1 - Bottom Layer 1" at 8433.61,7746.85 h60
  text "35" at 6830.75,7622.53 h60
  text "7.87mil (0.200mm)" at 7162.75,7622.53 h60
  text "PTH" at 7799.32,7622.53 h60
  text "Round" at 8058.46,7622.53 h60
  text "Top Layer 1 - Bottom Layer 1" at 8433.61,7622.53 h60
  text "180" at 6830.75,7498.21 h60
  text "10.00mil (0.254mm)" at 7162.75,7498.21 h60
  text "PTH" at 7799.32,7498.21 h60
  text "Round" at 8058.46,7498.21 h60
  text "Top Layer 1 - Bottom Layer 1" at 8433.61,7498.21 h60
  text "11" at 6830.75,7373.89 h60
  text "15.00mil (0.381mm)" at 7162.75,7373.89 h60
  text "PTH" at 7799.32,7373.89 h60
  text "Round" at 8058.46,7373.89 h60
  text "Top Layer 1 - Bottom Layer 1" at 8433.61,7373.89 h60
  text "14" at 6830.75,7249.57 h60
  text "15.75mil (0.400mm)" at 7162.75,7249.57 h60
  text "PTH" at 7799.32,7249.57 h60
  text "Round" at 8058.46,7249.57 h60
  text "Top Layer 1 - Bottom Layer 1" at 8433.61,7249.57 h60
  text "10" at 6830.75,7125.25 h60
  text "40.00mil (1.016mm)" at 7162.75,7125.25 h60
  text "PTH" at 7799.32,7125.25 h60
  text "Round" at 8058.46,7125.25 h60
  text "Top Layer 1 - Bottom Layer 1" at 8433.61,7125.25 h60
  text "5" at 6830.75,7000.93 h60
  text "40.16mil (1.020mm)" at 7162.75,7000.93 h60
  text "PTH" at 7799.32,7000.93 h60
  text "Round" at 8058.46,7000.93 h60
  text "Top Layer 1 - Bottom Layer 1" at 8433.61,7000.93 h60
  text "8" at 6830.75,6876.61 h60
  text "63.00mil (1.600mm)" at 7162.75,6876.61 h60
  text "PTH" at 7799.32,6876.61 h60
  text "Round" at 8058.46,6876.61 h60
  text "Top Layer 1 - Bottom Layer 1" at 8433.61,6876.61 h60
  text "4" at 6830.75,6752.29 h60
  text "170.00mil (4.318mm)" at 7162.75,6752.29 h60
  text "PTH" at 7799.32,6752.29 h60
  text "Round" at 8058.46,6752.29 h60
  text "Top Layer 1 - Bottom Layer 1" at 8433.61,6752.29 h60
  text "2" at 6830.75,6627.97 h60
  text "33.47mil (0.850mm)" at 7162.75,6627.97 h60
  text "PTH" at 7799.32,6627.97 h60
  text "Slot" at 8058.46,6627.97 h60
  text "Top Layer 1 - Bottom Layer 1" at 8433.61,6627.97 h60
  text "2" at 6830.75,6503.65 h60
  text "59.06mil (1.500mm)" at 7162.75,6503.65 h60
  text "PTH" at 7799.32,6503.65 h60
  text "Slot" at 8058.46,6503.65 h60
  text "Top Layer 1 - Bottom Layer 1" at 8433.61,6503.65 h60
  text "4" at 6830.75,6379.33 h60
  text "62.99mil (1.600mm)" at 7162.75,6379.33 h60
  text "PTH" at 7799.32,6379.33 h60
  text "Slot" at 8058.46,6379.33 h60
  text "Top Layer 1 - Bottom Layer 1" at 8433.61,6379.33 h60
  text "276 Total" at 6830.75,6255.01 h60
  text "Slot definitions :" at 6530.19,6167.99 h60
  text "Routed Path Length" at 6980.9,6167.99 h60
  text "= Calculated from tool start centre position to tool end centre position." at 7520.64,6167.99 h60
  text "Hole Length" at 6980.9,6118.26 h60
  text "= Routed Path Length + Tool Size = Slot length as defined in the PCB layout" at 7320.84,6118.26 h60
  text ".Layer_Name" at 577,-858.49 h60
M17 Embedded Cavity:
  text ".Layer_Name" at 577,-858.49 h60
M18 Embedded Assembly:
  text ".Layer_Name" at 577,-858.49 h60
M19 Embedded Keepout:
  text ".Layer_Name" at 577,-858.49 h60

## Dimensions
0,-400 to 1000,-400 on M2 Board Dimensions
0,0 to 0,2383 on M2 Board Dimensions
0,0 to 3834,0 on M2 Board Dimensions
